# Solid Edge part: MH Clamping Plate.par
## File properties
Author: davee
Template: Normal.par
Last saved by: davee
Revision: 7
Application: Solid Edge
Accuracy: 0.990
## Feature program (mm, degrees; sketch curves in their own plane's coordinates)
sketch for "unnamed Protrusion 1" plane through (0, 0, 0) normal (0, 0, 1) x-axis (1, 0, 0)
  line (-130, -100) -> (130, -100)
  line (130, -100) -> (130, 100)
  line (130, 100) -> (-130, 100)
  line (-130, 100) -> (-130, -100)
  dimension (linear) = 130
  dimension (linear) = 130
extrude "unnamed Protrusion 1" add finite 29.5 along +normal
sketch for "Hole_1" plane through (0, 0, 29.5) normal (0, 0, 1) x-axis (1, 0, 0)
  hole centre (80, 49) bore radius 6.25
hole "Hole_1" diameter 12.5 through  CounterBoreDepth = 12.5 mm; VBottomAngle = 118 deg
sketch for "unnamed Hole 1" plane through (0, 0, 29.5) normal (0, 0, 1) x-axis (1, 0, 0)
  hole centre (80, -49) bore radius 6.25
hole "unnamed Hole 1" through
sketch for "unnamed Hole 2" plane through (0, 0, 29.5) normal (0, 0, 1) x-axis (1, 0, 0)
  hole centre (-80, -49) bore radius 6.25
hole "unnamed Hole 2" through
sketch for "unnamed Hole 3" plane through (0, 0, 29.5) normal (0, 0, 1) x-axis (1, 0, 0)
  hole centre (-80, 49) bore radius 6.25
hole "unnamed Hole 3" through
pattern "unnamed Pattern 1" of "Hole_1", "unnamed Hole 1", "unnamed Hole 2", "unnamed Hole 3"
sketch for "ExtrudedCutout_1" plane through (0, 0, 0) normal (0, 0, -1) x-axis (1, 0, 0)
extrude "ExtrudedCutout_1" cut finite 66.675 along -normal
sketch for "ExtrudedCutout_2" plane through (0, 0, 29.5) normal (0, 0, 1) x-axis (1, 0, 0)
extrude "ExtrudedCutout_2" cut finite 63.5 along -normal
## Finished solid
Body 1: solid body, 20 faces, 32 edges, 8 vertices.
  Faces by surface: cylinder 10, plane 10
  Edges by curve: circle 20, line 12
Bounding box of the edges (mm): 260.000 x 200.000 x 29.500, from (-130, -100, 0) to (130, 100, 29.5).
Cylindrical faces by radius (mm): R3 x1, R6.25 x4, R9.5 x4, R19 x1
Planar faces by outward normal: +x 1, +y 1, +z 5, -x 1, -y 1, -z 1
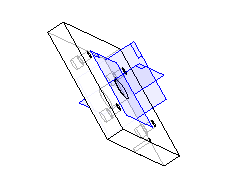
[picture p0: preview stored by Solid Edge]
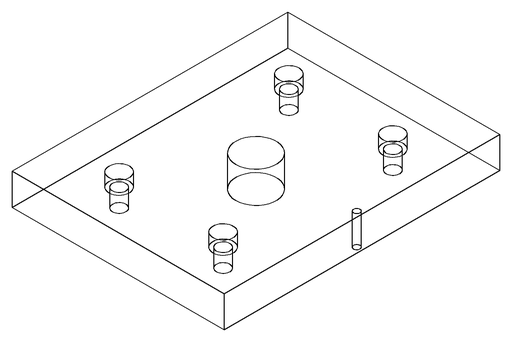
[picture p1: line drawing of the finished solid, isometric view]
